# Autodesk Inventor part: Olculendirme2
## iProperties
Created: 2004-07
Part Number: Olculendirme2
Document SubType Name: Modeling
Designer: Admin
Manufacturer: Standard
Standards Organization: Custom
Density: 1 g/cm^3
Author: Admin
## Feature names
1. Revolution1
2. Chamfer1
3. Extrusion1
4. Extrusion2
